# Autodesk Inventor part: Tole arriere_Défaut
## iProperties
Shininess: 64.0
Length Units: 11269
Angle Units: 11279
Time Units: 11290
Mass Units: 11283
Length Display Precision: 3
Angle Display Precision: 2
Compacted: True
Part Number: Tole arriere_Défaut
Document SubType Name: Modeling
Created: 2006-01
Material: Par défaut
Designer: Fricot
Density: 0.0
Volumn: 0.0
Area: 0.0
PropertySet Name: Model Information
Control State: 0
Master: False
Checked Out: False
Author: Fricot
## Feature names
1. Base1
